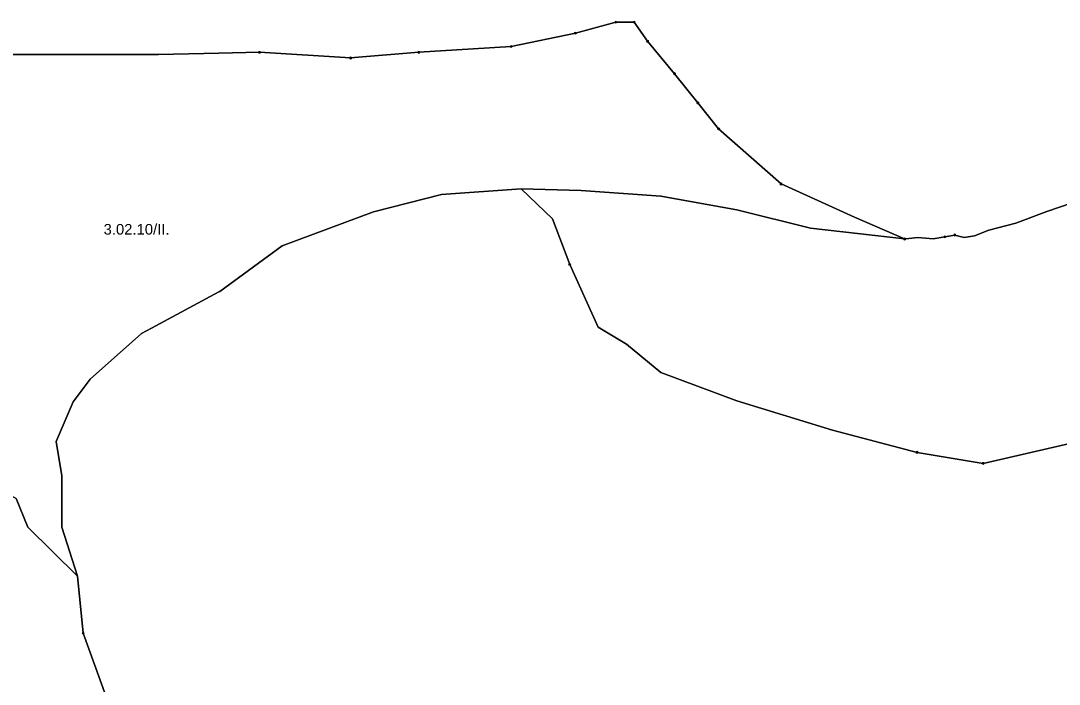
# Model space of a CAD drawing. Extents: x -650455 to -642254, y -1075222 to -1066610.
# Drawn here: x -647688 to -646705, y -1070337 to -1069709 of the extents above; entities that cross this region are included whole.
import ezdxf
from ezdxf.enums import TextEntityAlignment as Align

# ---------------------------------------------------------------- set-up
doc = ezdxf.new("R2010")
doc.units = 0
doc.header["$LTSCALE"] = 4
doc.header["$PDMODE"] = 32
doc.header["$PDSIZE"] = 2
for name, color, linetype, lineweight in [('1', 7, 'Continuous', 25), ('11', 7, 'Continuous', 13), ('12', 7, 'Continuous', 13), ('13', 7, 'Continuous', 13)]:
    doc.layers.add(name, color=color, linetype=linetype, lineweight=lineweight)
doc.layers.add('2', color=7, linetype='Continuous')

msp = doc.modelspace()

# ---------------------------------------------------------------- linework, layer by layer
at = {"layer": '1'}
for points in [[(-646850.869, -1069915.694), (-646849.651, -1069915.559), (-646838.507, -1069914.323), (-646823.887, -1069915.492), (-646812.777, -1069913.738), (-646803.42, -1069911.984), (-646794.649, -1069914.323), (-646784.708, -1069912.568), (-646771.258, -1069907.305), (-646745.528, -1069900.873), (-646716.29, -1069889.762), (-646692.314, -1069881.576), (-646671.847, -1069875.143), (-646654.889, -1069873.389), (-646615.709, -1069847.074), (-646606.5, -1069833.5), (-646563.5, -1069794), (-646468.5, -1069688)], [(-646468.5, -1069688), (-646563.5, -1069794), (-646606.5, -1069833.5), (-646615.709, -1069847.074), (-646654.889, -1069873.389), (-646671.847, -1069875.143), (-646692.314, -1069881.576), (-646716.29, -1069889.762), (-646745.528, -1069900.873), (-646771.258, -1069907.305), (-646784.708, -1069912.568), (-646794.649, -1069914.323), (-646803.42, -1069911.984), (-646812.777, -1069913.738), (-646823.887, -1069915.492), (-646838.507, -1069914.323), (-646849.651, -1069915.559), (-646850.869, -1069915.694)], [(-646850.869, -1069915.694), (-646898.307, -1069894.972), (-646967.86, -1069863.673), (-647026.98, -1069811.508), (-647046.57, -1069787.021), (-647068.712, -1069759.344), (-647094.22, -1069728.734), (-647106.966, -1069710.656), (-647124.354, -1069710.656), (-647162.609, -1069721.089), (-647223.405, -1069733.666), (-647310.714, -1069739.123), (-647375.348, -1069744.509), (-647461.527, -1069739.123), (-647500, -1069739.935), (-647557.131, -1069741.143), (-647621.765, -1069741.143), (-647734.874, -1069741.143)], [(-647310.714, -1069739.123), (-647223.405, -1069733.666), (-647162.609, -1069721.089), (-647124.354, -1069710.656), (-647106.966, -1069710.656), (-647094.22, -1069728.734), (-647068.712, -1069759.344), (-647046.57, -1069787.021), (-647026.98, -1069811.508), (-646967.86, -1069863.673), (-646898.307, -1069894.972), (-646850.869, -1069915.694)], [(-647734.874, -1069741.143), (-647621.765, -1069741.143), (-647557.131, -1069741.143), (-647500, -1069739.935), (-647461.527, -1069739.123), (-647375.348, -1069744.509), (-647310.714, -1069739.123)], [(-646850.869, -1069915.694), (-646940.039, -1069905.405), (-647009.592, -1069888.017), (-647081.803, -1069875.123), (-647157.209, -1069869.737), (-647213.764, -1069868.391), (-647289.17, -1069873.777), (-647353.804, -1069889.935), (-647439.982, -1069922.253), (-647499.23, -1069965.342), (-647500, -1069965.755), (-647563.848, -1070000), (-647573.29, -1070005.065), (-647621.766, -1070048.154), (-647637.924, -1070069.699), (-647654.082, -1070107.402), (-647648.696, -1070139.719), (-647648.696, -1070188.194), (-647633.884, -1070234.65), (-647681.013, -1070188.194), (-647691.786, -1070161.263)], [(-647606.954, -1070347.759), (-647628.498, -1070288.512), (-647633.884, -1070234.65), (-647648.696, -1070188.194), (-647648.696, -1070139.719), (-647654.082, -1070107.402), (-647637.924, -1070069.699), (-647621.766, -1070048.154), (-647573.29, -1070005.065), (-647563.848, -1070000), (-647500, -1069965.755), (-647499.23, -1069965.342), (-647439.982, -1069922.253), (-647353.804, -1069889.935), (-647289.17, -1069873.777), (-647213.764, -1069868.391), (-647184.14, -1069896.668), (-647167.981, -1069939.757), (-647141.05, -1069999.005), (-647139.392, -1070000), (-647114.12, -1070015.164), (-647081.803, -1070042.095), (-647009.592, -1070068.855), (-646919.173, -1070096.676), (-646839.187, -1070117.542), (-646776.589, -1070127.975), (-646686.17, -1070107.109)], [(-646686.17, -1070107.109), (-646776.589, -1070127.975), (-646839.187, -1070117.542), (-646919.173, -1070096.676), (-647009.592, -1070068.855), (-647081.803, -1070042.095), (-647114.12, -1070015.164), (-647139.392, -1070000), (-647141.05, -1069999.005), (-647167.981, -1069939.757), (-647184.14, -1069896.668), (-647213.764, -1069868.391), (-647157.209, -1069869.737), (-647081.803, -1069875.123), (-647009.592, -1069888.017), (-646940.039, -1069905.405), (-646850.869, -1069915.694)], [(-647811.031, -1070119.811), (-647804.895, -1070123.56), (-647767.192, -1070139.719), (-647729.489, -1070139.719), (-647691.786, -1070161.263), (-647681.013, -1070188.194), (-647633.884, -1070234.65), (-647628.498, -1070288.512), (-647606.954, -1070347.759), (-647601.567, -1070433.938), (-647585.409, -1070514.73), (-647558.478, -1070606.295), (-647547.706, -1070654.771), (-647515.389, -1070730.177), (-647460.18, -1070837.227), (-647390.16, -1070966.495), (-647320.14, -1071068.832), (-647244.734, -1071176.555), (-647277.051, -1071198.1), (-647260.893, -1071219.644)]]:
    msp.add_lwpolyline(points, dxfattribs=at)
at = {"layer": '11'}
for p, q in [((-647162.609, -1069721.089), (-647124.354, -1069710.656)), ((-647026.98, -1069811.508), (-646967.86, -1069863.673)), ((-646812.777, -1069913.738), (-646803.42, -1069911.984))]:
    msp.add_line(p, q, dxfattribs=at)
for points in [[(-647124.354, -1069710.656), (-647106.966, -1069710.656), (-647094.22, -1069728.734), (-647068.712, -1069759.344), (-647046.57, -1069787.021), (-647026.98, -1069811.508)], [(-647375.348, -1069744.509), (-647310.714, -1069739.123), (-647223.405, -1069733.666), (-647162.609, -1069721.089)], [(-647840.695, -1070000), (-647842.598, -1069994.291), (-647847.984, -1069924.272), (-647847.984, -1069848.866), (-647821.053, -1069778.845), (-647788.736, -1069751.914), (-647752.418, -1069744.651), (-647734.874, -1069741.143), (-647621.765, -1069741.143), (-647557.131, -1069741.143), (-647500, -1069739.935), (-647461.527, -1069739.123), (-647375.348, -1069744.509)], [(-646839.187, -1070117.542), (-646919.173, -1070096.676), (-647009.592, -1070068.855), (-647081.803, -1070042.095), (-647114.12, -1070015.164), (-647139.392, -1070000), (-647141.05, -1069999.005), (-647167.981, -1069939.757), (-647184.14, -1069896.668), (-647213.764, -1069868.391), (-647289.17, -1069873.777), (-647353.804, -1069889.935), (-647439.982, -1069922.253), (-647499.23, -1069965.342), (-647500, -1069965.755), (-647563.848, -1070000), (-647573.29, -1070005.065), (-647621.766, -1070048.154), (-647637.924, -1070069.699), (-647654.082, -1070107.402), (-647648.696, -1070139.719), (-647648.696, -1070188.194), (-647633.884, -1070234.65), (-647628.498, -1070288.512), (-647606.954, -1070347.759)], [(-646967.86, -1069863.673), (-646898.307, -1069894.972), (-646850.869, -1069915.694)], [(-646803.42, -1069911.984), (-646794.649, -1069914.323), (-646784.708, -1069912.568), (-646771.258, -1069907.305), (-646745.528, -1069900.873), (-646716.29, -1069889.762), (-646692.314, -1069881.576)], [(-646850.869, -1069915.694), (-646849.651, -1069915.559), (-646838.507, -1069914.323), (-646823.887, -1069915.492), (-646812.777, -1069913.738)], [(-646686.17, -1070107.109), (-646776.589, -1070127.975), (-646839.187, -1070117.542)]]:
    msp.add_lwpolyline(points, dxfattribs=at)
for p in [(-647124.354, -1069710.656), (-647162.609, -1069721.089), (-647375.348, -1069744.509), (-647026.98, -1069811.508), (-646967.86, -1069863.673), (-646850.869, -1069915.694), (-646812.777, -1069913.738), (-646803.42, -1069911.984), (-646839.187, -1070117.542)]:
    msp.add_point(p, dxfattribs=at)
at = {"layer": '12'}
for p, q in [((-647094.22, -1069728.734), (-647106.966, -1069710.656)), ((-647068.712, -1069759.344), (-647094.22, -1069728.734)), ((-647223.405, -1069733.666), (-647310.714, -1069739.123)), ((-647046.57, -1069787.021), (-647068.712, -1069759.344))]:
    msp.add_line(p, q, dxfattribs=at)
for points in [[(-647106.966, -1069710.656), (-647124.354, -1069710.656), (-647162.609, -1069721.089), (-647223.405, -1069733.666)], [(-647461.527, -1069739.123), (-647500, -1069739.935), (-647557.131, -1069741.143), (-647621.765, -1069741.143), (-647734.874, -1069741.143), (-647752.418, -1069744.651), (-647788.736, -1069751.914), (-647821.053, -1069778.845), (-647847.984, -1069848.866), (-647847.984, -1069924.272), (-647842.598, -1069994.291), (-647840.695, -1070000), (-647826.44, -1070042.768), (-647811.031, -1070119.811)], [(-647310.714, -1069739.123), (-647375.348, -1069744.509), (-647461.527, -1069739.123)], [(-647691.786, -1070161.263), (-647681.013, -1070188.194), (-647633.884, -1070234.65), (-647648.696, -1070188.194), (-647648.696, -1070139.719), (-647654.082, -1070107.402), (-647637.924, -1070069.699), (-647621.766, -1070048.154), (-647573.29, -1070005.065), (-647563.848, -1070000), (-647500, -1069965.755), (-647499.23, -1069965.342), (-647439.982, -1069922.253), (-647353.804, -1069889.935), (-647289.17, -1069873.777), (-647213.764, -1069868.391), (-647157.209, -1069869.737), (-647081.803, -1069875.123), (-647009.592, -1069888.017), (-646940.039, -1069905.405), (-646850.869, -1069915.694), (-646898.307, -1069894.972), (-646967.86, -1069863.673), (-647026.98, -1069811.508), (-647046.57, -1069787.021)], [(-647628.498, -1070288.512), (-647633.884, -1070234.65), (-647681.013, -1070188.194), (-647691.786, -1070161.263), (-647729.489, -1070139.719), (-647767.192, -1070139.719), (-647804.895, -1070123.56), (-647811.031, -1070119.811), (-647842.598, -1070096.63), (-647901.846, -1070064.312), (-647901.846, -1070080.471)], [(-647283.784, -1071309.189), (-647266.279, -1071246.575), (-647260.893, -1071219.644), (-647277.051, -1071198.1), (-647244.734, -1071176.555), (-647320.14, -1071068.832), (-647390.16, -1070966.495), (-647460.18, -1070837.227), (-647515.389, -1070730.177), (-647547.706, -1070654.771), (-647558.478, -1070606.295), (-647585.409, -1070514.73), (-647601.567, -1070433.938), (-647606.954, -1070347.759), (-647628.498, -1070288.512)]]:
    msp.add_lwpolyline(points, dxfattribs=at)
for p in [(-647106.966, -1069710.656), (-647223.405, -1069733.666), (-647094.22, -1069728.734), (-647461.527, -1069739.123), (-647310.714, -1069739.123), (-647068.712, -1069759.344), (-647046.57, -1069787.021), (-647628.498, -1070288.512)]:
    msp.add_point(p, dxfattribs=at)
at = {"layer": '13'}
for points in [[(-646692.314, -1069881.576), (-646716.29, -1069889.762), (-646745.528, -1069900.873), (-646771.258, -1069907.305), (-646784.708, -1069912.568), (-646794.649, -1069914.323), (-646803.42, -1069911.984), (-646812.777, -1069913.738), (-646823.887, -1069915.492), (-646838.507, -1069914.323), (-646849.651, -1069915.559), (-646850.869, -1069915.694), (-646940.039, -1069905.405), (-647009.592, -1069888.017), (-647081.803, -1069875.123), (-647157.209, -1069869.737), (-647213.764, -1069868.391), (-647184.14, -1069896.668), (-647167.981, -1069939.757)], [(-647167.981, -1069939.757), (-647141.05, -1069999.005), (-647139.392, -1070000), (-647114.12, -1070015.164), (-647081.803, -1070042.095), (-647009.592, -1070068.855), (-646919.173, -1070096.676), (-646839.187, -1070117.542), (-646776.589, -1070127.975)], [(-646776.589, -1070127.975), (-646686.17, -1070107.109), (-646602.706, -1070072.333)]]:
    msp.add_lwpolyline(points, dxfattribs=at)
for p in [(-647167.981, -1069939.757), (-646776.589, -1070127.975)]:
    msp.add_point(p, dxfattribs=at)

# ---------------------------------------------------------------- texts
at = {"layer": '2', "width": 1.05}
msp.add_text('3.02.10/II.', height=10, dxfattribs=at).set_placement((-647577.975, -1069911.549), align=Align.CENTER)

doc.saveas('drawing.dxf')
